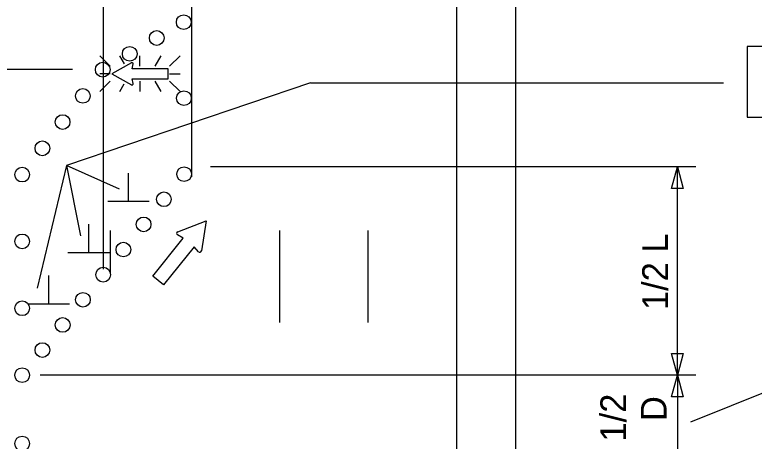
# Model space of a CAD drawing. Extents: x 16038 to 19504, y 5710 to 8321.
# Drawn here: x 17002.7 to 17203.6, y 6496.9 to 6612.8 of the extents above; entities that cross this region are included whole.
import ezdxf

# ---------------------------------------------------------------- set-up
doc = ezdxf.new("R2010")
doc.units = 0
for name, color, linetype in [('ALI_LEGAL_EX', 7, 'Continuous'), ('MT_SCRATCH_LEVEL_E', 7, 'Continuous'), ('PAVT_EDGE_EX', 7, 'Continuous'), ('TRAFFIC_SIGNS_PR', 7, 'Continuous'), ('TYPICAL_TEXT_DIMEN_PR', 7, 'Continuous')]:
    doc.layers.add(name, color=color, linetype=linetype)

msp = doc.modelspace()

# ---------------------------------------------------------------- linework, layer by layer
at = {"layer": 'ALI_LEGAL_EX'}
for points in [[(17028.71, 6542.73), (17028.71, 6554.12)], [(17074.71, 6529.12), (17074.71, 6554.12)], [(17098.71, 6529.12), (17098.71, 6554.12)]]:
    msp.add_lwpolyline(points, dxfattribs=at)
at = {"layer": 'MT_SCRATCH_LEVEL_E'}
for p, q in [((17046.96, 6553.77), (17054.73, 6556.81)), ((17046.96, 6553.77), (17054.73, 6556.81)), ((17054.73, 6556.81), (17053.39, 6548.59)), ((17054.73, 6556.81), (17053.39, 6548.59)), ((17048.49, 6552.06), (17046.91, 6552.93)), ((17048.49, 6552.06), (17046.91, 6552.93)), ((17040.17, 6541.74), (17048.49, 6552.06)), ((17040.17, 6541.74), (17048.49, 6552.06)), ((17051.4, 6549.72), (17043.09, 6539.39)), ((17051.4, 6549.72), (17043.09, 6539.39)), ((17052.59, 6548.36), (17051.4, 6549.72)), ((17052.59, 6548.36), (17051.4, 6549.72)), ((17043.09, 6539.39), (17040.17, 6541.74)), ((17043.09, 6539.39), (17040.17, 6541.74))]:
    msp.add_line(p, q, dxfattribs=at)
for centre, start, end in [((17047.14, 6553.34), 111.3861, 241.123), ((17047.14, 6553.34), 111.3861, 241.123), ((17052.94, 6548.67), 221.1954, 350.7344), ((17052.94, 6548.67), 221.1954, 350.7344)]:
    msp.add_arc(centre, 0.463, start, end, dxfattribs=at)
at = {"layer": 'PAVT_EDGE_EX'}
for p, q in [((17026.71, 6925.32), (17026.71, 6544.7)), ((17050.71, 6925.32), (17050.71, 6570.98)), ((17122.71, 6925.32), (17122.71, 6077.44)), ((17138.71, 6925.32), (17138.71, 6077.44)), ((17026.71, 6816.67), (17026.71, 6543.65)), ((17050.71, 6816.67), (17050.71, 6568.76))]:
    msp.add_line(p, q, dxfattribs=at)
at = {"layer": 'TRAFFIC_SIGNS_PR'}
for p, q in [((17025.79, 6601.61), (17028.61, 6598.79)), ((17032.51, 6599.43), (17031.25, 6601.61)), ((17036.7, 6598.79), (17036.7, 6601.61)), ((17040.83, 6598.79), (17042.46, 6601.61)), ((17044.78, 6598.79), (17047.6, 6601.61)), ((17028.61, 6596.76), (17025.79, 6596.76)), ((17044.78, 6596.76), (17047.6, 6596.76)), ((17025.79, 6591.91), (17028.61, 6594.73)), ((17036.7, 6594.73), (17036.7, 6591.91)), ((17042.49, 6591.91), (17040.86, 6594.73)), ((17044.78, 6594.73), (17047.6, 6591.91)), ((17031.23, 6591.91), (17032.44, 6594))]:
    msp.add_line(p, q, dxfattribs=at)
msp.add_lwpolyline([(17201.65, 6584.95), (17240.05, 6584.95), (17240.05, 6604.15), (17201.65, 6604.15)], close=True, dxfattribs=at)
for points in [[(17034.37, 6599.78), (17029.06, 6596.76), (17034.37, 6593.72)], [(17034.87, 6594.08), (17034.64, 6595.37), (17044.36, 6595.37), (17044.36, 6598.12), (17034.64, 6598.12), (17034.87, 6599.42)]]:
    msp.add_lwpolyline(points, dxfattribs=at)
for centre in [(17048.6, 6610.8), (17048.6, 6610.8), (17041.27, 6606.49), (17033.94, 6602.19), (17026.61, 6597.88), (17021.19, 6590.75), (17048.65, 6590.13), (17015.7, 6583.62), (17010.2, 6576.49), (17004.71, 6569.36), (17004.71, 6569.36), (17004.71, 6569.36), (17004.71, 6569.36), (17004.71, 6569.36), (17048.71, 6569.46), (17043.21, 6562.63), (17037.71, 6555.8), (17004.71, 6551.18), (17032.21, 6548.97), (17026.71, 6542.14), (17021.21, 6535.31), (17004.71, 6533), (17015.71, 6528.48), (17010.21, 6521.65), (17004.71, 6514.82), (17004.71, 6514.82), (17004.71, 6496.23)]:
    msp.add_circle(centre, 2, dxfattribs=at)
for centre, start, end in [((17034.53, 6599.48), 350.7308, 118.8916), ((17034.53, 6594.02), 241.4833, 9.9593)]:
    msp.add_arc(centre, 0.341, start, end, dxfattribs=at)
at = {"layer": 'TYPICAL_TEXT_DIMEN_PR'}
for p, q in [((17018.36, 6597.88), (16854.51, 6597.88)), ((17083.03, 6594.27), (17016.78, 6571.82)), ((17083.03, 6594.27), (17195.22, 6594.27)), ((17016.78, 6571.82), (17008.81, 6538.48)), ((17031.18, 6565.37), (17016.78, 6571.82)), ((17016.78, 6571.82), (17020.55, 6552.7)), ((17187.71, 6571.46), (17055.85, 6571.46)), ((17181.14, 6565.6), (17182.71, 6571.46)), ((17182.71, 6514.82), (17182.71, 6571.46)), ((17182.71, 6571.46), (17184.28, 6565.6)), ((17033.62, 6562), (17033.62, 6569.78)), ((17182.71, 6565.6), (17181.14, 6565.6)), ((17184.28, 6565.6), (17182.71, 6565.6)), ((17039.24, 6562), (17027.99, 6562)), ((17022.79, 6548.07), (17022.79, 6555.86)), ((17028.41, 6548.07), (17017.16, 6548.07)), ((17011.96, 6534.15), (17011.96, 6541.93)), ((17017.58, 6534.15), (17006.33, 6534.15)), ((17182.71, 6514.82), (17181.14, 6520.68)), ((17181.14, 6520.68), (17182.71, 6520.68)), ((17182.71, 6520.68), (17184.28, 6520.68)), ((17184.28, 6520.68), (17182.71, 6514.82)), ((17187.71, 6514.82), (17009.59, 6514.82)), ((17181.14, 6508.96), (17182.71, 6514.82)), ((17182.71, 6514.82), (17184.28, 6508.96)), ((17182.71, 6514.82), (17182.71, 6490.36)), ((17220.27, 6515.7), (17186.28, 6502.03)), ((17182.71, 6508.96), (17181.14, 6508.96)), ((17184.28, 6508.96), (17182.71, 6508.96))]:
    msp.add_line(p, q, dxfattribs=at)

# ---------------------------------------------------------------- texts
for s, p in [('1/2 L', (17180.15, 6532.52)), ('1/2', (17168.78, 6496.78)), ('D', (17179.78, 6502.35))]:
    msp.add_text(s, height=7, rotation=90, dxfattribs=at).set_placement(p)

doc.saveas('drawing.dxf')
